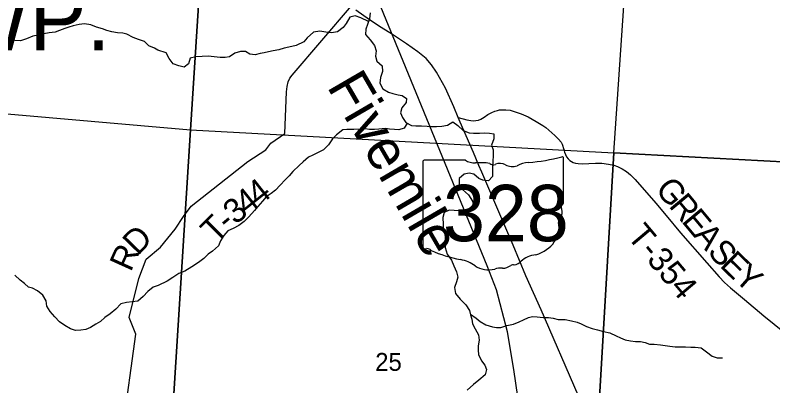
# Model space of a CAD drawing. Extents: x 0 to 34, y 0 to 22.
# Drawn here: x 4.184 to 5.957, y 19.32 to 20.186 of the extents above; entities that cross this region are included whole.
import ezdxf

# ---------------------------------------------------------------- set-up
doc = ezdxf.new("R2010")
doc.units = 0
for name, color, linetype in [('GM_X_Corporation', 7, 'Continuous'), ('GM_X_Minor_River', 7, 'Continuous'), ('GM_X_Minor_River_Text', 7, 'Continuous'), ('GM_X_Rail_Line', 7, 'Continuous'), ('GM_X_Section_Text', 7, 'Continuous'), ('GM_X_State_Location', 7, 'Continuous'), ('GM_X_State_Route', 7, 'Continuous'), ('GM_X_State_Shield', 7, 'Continuous'), ('GM_X_Township_Road', 7, 'Continuous'), ('GM_X_Township_Road_Text', 7, 'Continuous'), ('GM_X_Township_Text', 7, 'Continuous')]:
    doc.layers.add(name, color=color, linetype=linetype)

msp = doc.modelspace()

# ---------------------------------------------------------------- linework, layer by layer
at = {"layer": 'GM_X_Corporation'}
for points in [[(4.6577, 20.9), (3.646, 20.9), (3.5832, 20.0065), (4.594, 19.9182)], [(5.5834, 20.9), (4.6577, 20.9), (4.594, 19.9182), (5.5855, 19.8646), (5.6551, 20.8957), (5.6507, 20.896)], [(5.6551, 20.8957), (6.6504, 20.8365), (6.5798, 19.8114), (5.5855, 19.8646)], [(3.5832, 20.0065), (4.594, 19.9182), (4.5309, 18.9179), (4.5247, 18.9179), (3.5166, 18.9866)], [(4.594, 19.9182), (5.5855, 19.8646), (5.5263, 18.8526), (4.5309, 18.9179)], [(5.5855, 19.8646), (6.5798, 19.8114), (6.5391, 18.7835), (5.5263, 18.8526)]]:
    msp.add_lwpolyline(points, close=True, dxfattribs=at)
at = {"layer": 'GM_X_Minor_River'}
for p, q in [((4.9797, 20.1846), (4.9677, 20.1818)), ((4.9934, 20.1798), (4.9797, 20.1846)), ((4.3339, 20.1647), (4.3195, 20.1616)), ((4.3464, 20.1659), (4.3339, 20.1647)), ((4.3608, 20.1637), (4.3464, 20.1659)), ((4.9587, 20.1669), (4.952, 20.1574)), ((4.9677, 20.1818), (4.9587, 20.1669)), ((5.011, 20.1719), (4.9934, 20.1798)), ((4.2878, 20.1501), (4.2776, 20.1467)), ((4.2999, 20.1551), (4.2878, 20.1501)), ((4.3097, 20.1585), (4.2999, 20.1551)), ((4.3195, 20.1616), (4.3097, 20.1585)), ((4.3744, 20.1585), (4.3608, 20.1637)), ((4.3884, 20.154), (4.3744, 20.1585)), ((4.3987, 20.1502), (4.3884, 20.154)), ((4.4104, 20.1472), (4.3987, 20.1502)), ((4.4233, 20.145), (4.4104, 20.1472)), ((4.8972, 20.1493), (4.8825, 20.1462)), ((4.9108, 20.1468), (4.8972, 20.1493)), ((4.9381, 20.1474), (4.9245, 20.145)), ((4.952, 20.1574), (4.9381, 20.1474)), ((4.2103, 20.1312), (4.1966, 20.1262)), ((4.2254, 20.1373), (4.2103, 20.1312)), ((4.2382, 20.1393), (4.2254, 20.1373)), ((4.2507, 20.1424), (4.2382, 20.1393)), ((4.2636, 20.1451), (4.2507, 20.1424)), ((4.2776, 20.1467), (4.2636, 20.1451)), ((4.4358, 20.144), (4.4233, 20.145)), ((4.4456, 20.1421), (4.4358, 20.144)), ((4.46, 20.1338), (4.4456, 20.1421)), ((4.4729, 20.1297), (4.46, 20.1338)), ((4.4866, 20.1248), (4.4729, 20.1297)), ((4.8671, 20.1331), (4.8596, 20.1236)), ((4.8825, 20.1462), (4.8671, 20.1331)), ((4.9245, 20.145), (4.9108, 20.1468)), ((4.1966, 20.1262), (4.1834, 20.1269)), ((4.4972, 20.115), (4.4866, 20.1248)), ((4.5101, 20.109), (4.4972, 20.115)), ((4.8245, 20.1115), (4.8135, 20.1091)), ((4.8419, 20.1151), (4.8245, 20.1115)), ((4.8596, 20.1236), (4.8419, 20.1151)), ((4.5179, 20.1041), (4.5101, 20.109)), ((4.5371, 20.0983), (4.5179, 20.1041)), ((4.5444, 20.0851), (4.5371, 20.0983)), ((4.6982, 20.0971), (4.6855, 20.089)), ((4.7118, 20.1014), (4.6982, 20.0971)), ((4.7232, 20.1011), (4.7118, 20.1014)), ((4.7335, 20.0952), (4.7232, 20.1011)), ((4.746, 20.0938), (4.7335, 20.0952)), ((4.7573, 20.0965), (4.746, 20.0938)), ((4.7671, 20.0985), (4.7573, 20.0965)), ((4.7769, 20.1009), (4.7671, 20.0985)), ((4.7879, 20.1029), (4.7769, 20.1009)), ((4.8011, 20.1056), (4.7879, 20.1029)), ((4.8135, 20.1091), (4.8011, 20.1056)), ((4.5539, 20.0723), (4.5444, 20.0851)), ((4.5935, 20.0859), (4.5899, 20.0726)), ((4.6068, 20.0891), (4.5935, 20.0859)), ((4.6215, 20.09), (4.6068, 20.0891)), ((4.6355, 20.0905), (4.6215, 20.09)), ((4.6499, 20.0887), (4.6355, 20.0905)), ((4.6639, 20.0873), (4.6499, 20.0887)), ((4.6756, 20.0871), (4.6639, 20.0873)), ((4.6855, 20.089), (4.6756, 20.0871)), ((4.5668, 20.0679), (4.5539, 20.0723)), ((4.5797, 20.065), (4.5668, 20.0679)), ((4.5899, 20.0726), (4.5797, 20.065)), ((4.9507, 19.9179), (4.936, 19.9068)), ((4.9605, 19.9187), (4.9507, 19.9179)), ((4.9768, 19.9189), (4.9605, 19.9187)), ((4.9904, 19.9198), (4.9768, 19.9189)), ((5.0036, 19.9206), (4.9904, 19.9198)), ((5.0135, 19.9192), (5.0036, 19.9206)), ((5.0248, 19.9189), (5.0135, 19.9192)), ((5.035, 19.9194), (5.0248, 19.9189)), ((5.0505, 19.9214), (5.035, 19.9194)), ((5.06, 19.92), (5.0505, 19.9214)), ((5.0721, 19.9186), (5.06, 19.92)), ((5.0823, 19.9183), (5.0721, 19.9186)), ((5.0944, 19.9218), (5.0823, 19.9183)), ((5.1014, 19.9337), (5.0944, 19.9218)), ((4.936, 19.9068), (4.927, 19.8968)), ((4.9173, 19.8835), (4.9057, 19.8716)), ((4.927, 19.8968), (4.9173, 19.8835)), ((4.8932, 19.8655), (4.8804, 19.8593)), ((4.9057, 19.8716), (4.8932, 19.8655)), ((4.8706, 19.8539), (4.8582, 19.8432)), ((4.8804, 19.8593), (4.8706, 19.8539)), ((4.8485, 19.8347), (4.8342, 19.8206)), ((4.8582, 19.8432), (4.8485, 19.8347)), ((4.8252, 19.811), (4.8158, 19.8015)), ((4.8342, 19.8206), (4.8252, 19.811)), ((4.8158, 19.8015), (4.8042, 19.7885)), ((4.7937, 19.7774), (4.7832, 19.769)), ((4.8042, 19.7885), (4.7937, 19.7774)), ((4.7715, 19.7616), (4.7626, 19.7513)), ((4.7832, 19.769), (4.7715, 19.7616)), ((4.7626, 19.7513), (4.7517, 19.7387)), ((4.7442, 19.7292), (4.7311, 19.715)), ((4.7517, 19.7387), (4.7442, 19.7292)), ((4.7202, 19.704), (4.7078, 19.6948)), ((4.7311, 19.715), (4.7202, 19.704)), ((4.6946, 19.6871), (4.6818, 19.682)), ((4.7078, 19.6948), (4.6946, 19.6871)), ((4.6721, 19.6713), (4.6646, 19.6584)), ((4.6818, 19.682), (4.6721, 19.6713)), ((4.6646, 19.6584), (4.6598, 19.6469)), ((4.6459, 19.6343), (4.6361, 19.6278)), ((4.6598, 19.6469), (4.6459, 19.6343)), ((4.6256, 19.6175), (4.6128, 19.6082)), ((4.6361, 19.6278), (4.6256, 19.6175)), ((4.5974, 19.5979), (4.5809, 19.5875)), ((4.6128, 19.6082), (4.5974, 19.5979)), ((4.5669, 19.5824), (4.553, 19.5728)), ((4.5809, 19.5875), (4.5669, 19.5824)), ((4.196, 19.5664), (4.1831, 19.5785)), ((4.2055, 19.5589), (4.196, 19.5664)), ((4.5394, 19.5644), (4.5187, 19.5538)), ((4.553, 19.5728), (4.5394, 19.5644)), ((4.2153, 19.5506), (4.2055, 19.5589)), ((4.2248, 19.5476), (4.2153, 19.5506)), ((4.2366, 19.5416), (4.2248, 19.5476)), ((4.5068, 19.55), (4.4947, 19.5405)), ((4.5187, 19.5538), (4.5068, 19.55)), ((4.2491, 19.5314), (4.2366, 19.5416)), ((4.2567, 19.5186), (4.2491, 19.5314)), ((4.4834, 19.5283), (4.4709, 19.5172)), ((4.4947, 19.5405), (4.4834, 19.5283)), ((4.2583, 19.5061), (4.2567, 19.5186)), ((4.4316, 19.511), (4.4195, 19.4988)), ((4.4444, 19.5141), (4.4316, 19.511)), ((4.4577, 19.516), (4.4444, 19.5141)), ((4.4709, 19.5172), (4.4577, 19.516)), ((4.2662, 19.4936), (4.2583, 19.5061)), ((4.2769, 19.4808), (4.2662, 19.4936)), ((4.4195, 19.4988), (4.4067, 19.4882)), ((4.2875, 19.469), (4.2769, 19.4808)), ((4.3942, 19.4794), (4.3837, 19.4702)), ((4.4067, 19.4882), (4.3942, 19.4794)), ((5.2495, 19.487), (5.2629, 19.4777)), ((5.2629, 19.4777), (5.2724, 19.4699)), ((5.3639, 19.4692), (5.3737, 19.4742)), ((5.3737, 19.4742), (5.3854, 19.4796)), ((5.3854, 19.4796), (5.3952, 19.482)), ((5.3952, 19.482), (5.4058, 19.4806)), ((5.4058, 19.4806), (5.4195, 19.4795)), ((5.4195, 19.4795), (5.4323, 19.4793)), ((5.4323, 19.4793), (5.4429, 19.4775)), ((5.4429, 19.4775), (5.4551, 19.4746)), ((5.4551, 19.4746), (5.4717, 19.4743)), ((5.4717, 19.4743), (5.4865, 19.4714)), ((4.3, 19.4604), (4.2875, 19.469)), ((4.3133, 19.4529), (4.3, 19.4604)), ((4.3606, 19.4557), (4.3497, 19.4515)), ((4.3727, 19.4637), (4.3606, 19.4557)), ((4.3837, 19.4702), (4.3727, 19.4637)), ((5.2724, 19.4699), (5.2857, 19.4624)), ((5.2857, 19.4624), (5.3012, 19.4572)), ((5.3012, 19.4572), (5.3107, 19.4558)), ((5.3107, 19.4558), (5.3205, 19.4563)), ((5.3205, 19.4563), (5.3349, 19.461)), ((5.3349, 19.461), (5.3508, 19.4638)), ((5.3508, 19.4638), (5.3639, 19.4692)), ((5.4865, 19.4714), (5.4994, 19.4681)), ((5.4994, 19.4681), (5.5089, 19.4644)), ((5.5089, 19.4644), (5.5211, 19.4581)), ((5.5211, 19.4581), (5.5347, 19.4537)), ((4.3254, 19.4491), (4.3133, 19.4529)), ((4.3379, 19.4496), (4.3254, 19.4491)), ((4.3497, 19.4515), (4.3379, 19.4496)), ((5.5347, 19.4537), (5.5469, 19.4504)), ((5.5469, 19.4504), (5.5613, 19.4463)), ((5.5613, 19.4463), (5.5761, 19.4431)), ((5.5761, 19.4431), (5.5909, 19.4368)), ((5.5909, 19.4368), (5.6007, 19.4319)), ((5.6007, 19.4319), (5.6114, 19.4275)), ((5.6114, 19.4275), (5.6243, 19.4246)), ((5.6243, 19.4246), (5.636, 19.4231)), ((5.636, 19.4231), (5.6474, 19.4229)), ((5.6474, 19.4229), (5.6587, 19.4207)), ((5.6587, 19.4207), (5.669, 19.417)), ((5.669, 19.417), (5.6799, 19.4171)), ((5.6799, 19.4171), (5.6943, 19.4153)), ((5.6943, 19.4153), (5.7053, 19.4135)), ((5.7053, 19.4135), (5.7163, 19.4121)), ((5.7163, 19.4121), (5.7292, 19.4104)), ((5.7292, 19.4104), (5.753, 19.4106)), ((5.753, 19.4106), (5.7655, 19.4099)), ((5.7655, 19.4099), (5.7754, 19.4096)), ((5.7754, 19.4096), (5.7897, 19.4083)), ((5.7897, 19.4083), (5.8019, 19.3993)), ((5.8019, 19.3993), (5.8153, 19.3888)), ((5.8153, 19.3888), (5.827, 19.3847)), ((5.827, 19.3847), (5.8399, 19.3848))]:
    msp.add_line(p, q, dxfattribs=at)
for points in [[(5.0152, 20.1917), (5.0131, 20.178), (5.0087, 20.1647), (5.0046, 20.1537), (5.004, 20.1408), (5.0147, 20.1284), (5.0254, 20.1156), (5.0289, 20.1031), (5.0275, 20.0906), (5.0306, 20.0785), (5.0432, 20.0677), (5.0441, 20.0548), (5.0393, 20.0407), (5.0375, 20.0274), (5.0444, 20.0139), (5.0577, 20.0064), (5.0676, 20.0031), (5.0805, 19.9998), (5.09, 19.9984), (5.1002, 19.9916), (5.0995, 19.9821), (5.0891, 19.9699), (5.0861, 19.9582), (5.0908, 19.9472), (5.0981, 19.9355), (5.1114, 19.9281), (5.122, 19.9274), (5.1352, 19.9275), (5.1481, 19.9265), (5.1579, 19.9258), (5.17, 19.9256), (5.1829, 19.9264), (5.1961, 19.9292), (5.2082, 19.9369), (5.22, 19.9283), (5.2325, 19.9167), (5.2466, 19.9111), (5.2564, 19.9101), (5.2712, 19.9106), (5.2818, 19.911), (5.2946, 19.9104), (5.3041, 19.909), (5.3046, 19.8969), (5.2987, 19.8824), (5.3029, 19.8711), (5.3031, 19.8574), (5.3017, 19.8449), (5.3014, 19.8313), (5.3015, 19.8184), (5.3012, 19.8089), (5.2918, 19.7986), (5.2786, 19.8004), (5.2691, 19.8044), (5.2573, 19.8146), (5.247, 19.8171), (5.2346, 19.8147), (5.2229, 19.804), (5.2234, 19.7911), (5.2307, 19.7787), (5.2448, 19.766), (5.2548, 19.7516), (5.2564, 19.7388), (5.244, 19.728), (5.2323, 19.7276), (5.2228, 19.729), (5.2115, 19.7293), (5.2001, 19.7303), (5.1884, 19.7249), (5.1847, 19.7135), (5.1856, 19.6972), (5.1861, 19.6866), (5.19, 19.6756), (5.1908, 19.6658), (5.1906, 19.6525), (5.1907, 19.6427), (5.1953, 19.6276), (5.2049, 19.6136), (5.2111, 19.6)], [(5.2111, 19.6), (5.2169, 19.5861), (5.22, 19.574), (5.2171, 19.563), (5.2123, 19.5493), (5.2147, 19.5353), (5.2258, 19.5225), (5.2387, 19.5093), (5.2472, 19.4954), (5.2499, 19.4856), (5.2527, 19.4754), (5.2546, 19.4648), (5.2604, 19.4527), (5.2685, 19.4391), (5.2697, 19.4263), (5.268, 19.4134), (5.2677, 19.4031), (5.2685, 19.3925), (5.2754, 19.3782), (5.2831, 19.368), (5.2874, 19.3578), (5.2841, 19.3449), (5.269, 19.3327), (5.2566, 19.3227), (5.242, 19.3097)]]:
    msp.add_lwpolyline(points, dxfattribs=at)
at = {"layer": 'GM_X_Rail_Line'}
msp.add_lwpolyline([(5.4004, 18.0178), (5.3565, 18.3179), (5.3392, 18.4015), (5.2983, 18.5634), (5.2919, 18.587), (5.2905, 18.6045), (5.2864, 18.6295), (5.2867, 18.6593), (5.2915, 18.6851), (5.3496, 18.8224), (5.3806, 18.8744), (5.3985, 18.9151), (5.4041, 18.9575), (5.4041, 18.9937), (5.4016, 19.0373), (5.3783, 19.1779), (5.37, 19.2302), (5.351, 19.3574), (5.3362, 19.4456), (5.311, 19.5437), (5.2889, 19.5998), (5.0925, 20.0787), (5.0288, 20.2329)], dxfattribs=at)
at = {"layer": 'GM_X_State_Route'}
msp.add_lwpolyline([(5.5021, 19.2979), (5.4152, 19.4973), (5.3972, 19.5369), (5.3796, 19.5766), (5.3493, 19.6481), (5.3322, 19.6881), (5.276, 19.8195), (5.2696, 19.8345), (5.2565, 19.8652), (5.2256, 19.9365), (5.2212, 19.9469), (5.2105, 19.9718), (5.1916, 20.016), (5.1699, 20.0534), (5.1586, 20.0705), (5.1461, 20.0853), (5.1268, 20.1002), (5.0996, 20.1196), (5.067, 20.1414), (5.0406, 20.1578), (5.0133, 20.1753), (4.9815, 20.1978)], dxfattribs=at)
at = {"layer": 'GM_X_State_Shield'}
for p, q in [((5.2377, 19.8471), (5.1412, 19.8471)), ((5.4675, 19.7474), (5.4675, 19.8521)), ((5.1379, 19.8437), (5.1379, 19.6436)), ((5.4675, 19.7474), (5.4675, 19.7474))]:
    msp.add_line(p, q, dxfattribs=at)
for centre, major_axis, start_param, end_param in [((5.1417, 19.8441), (0.00382, 0), 1.712693, 3.28349), ((5.2607, 19.8703), (0.037, 0), 4.042523, 4.731795), ((5.3501, 20.1199), (0.3495, 0), 4.814394, 5.042369), ((5.4638, 19.8525), (0.00367, 0), 6.141152, 7.989035), ((5.2729, 19.7348), (0.133, 0), 1.404758, 1.657858), ((5.3031, 19.8451), (0.0107, 0), 3.836095, 5.185415), ((5.3188, 19.822), (0.0222, 0), 0.950623, 2.079405), ((5.3475, 19.8537), (0.0267, 0), 4.081561, 5.145723), ((5.3947, 19.786), (0.0703, 0), 1.699011, 2.107814), ((5.4666, 19.7397), (0.00568, 0), 1.883978, 3.671073), ((5.4636, 19.747), (0.00393, 0), 5.05454, 6.418171), ((5.4305, 19.7265), (0.0341, 0), 5.934695, 6.695948), ((5.4806, 19.7036), (0.0248, 0), 2.387724, 3.262537), ((5.3697, 19.6903), (0.0874, 0), 5.101752, 6.440018), ((5.1417, 19.6431), (0.00385, 0), 3.00124, 4.508301), ((5.1423, 19.6636), (0.0294, 0), 4.665946, 4.897461), ((5.1483, 19.632), (0.0106, 0), 0.519207, 1.627899), ((5.2821, 19.8118), (0.2524, 0), 4.195997, 4.488961), ((5.2069, 19.5536), (0.079, 0), 0.823519, 1.323587), ((5.4065, 19.5874), (0.0479, 0), 1.647645, 2.488434), ((5.2923, 19.631), (0.0501, 0), 4.026481, 4.996735), ((5.3249, 19.616), (0.0267, 0), 4.691044, 5.507374), ((5.3491, 19.5966), (0.00752, 0), 1.147584, 2.315152), ((5.3459, 19.6242), (0.0282, 0), 4.937069, 5.64225), ((5.3213, 19.5618), (0.0412, 0), 1.495662, 1.94098)]:
    msp.add_ellipse(centre, major_axis=major_axis, ratio=0.8, start_param=start_param, end_param=end_param, dxfattribs=at)
at = {"layer": 'GM_X_Township_Road'}
for points in [[(4.3419, 19.0241), (4.372, 19.0711), (4.3947, 19.1216), (4.4137, 19.1482), (4.43, 19.1766), (4.4357, 19.2192), (4.4663, 19.4401), (4.4508, 19.4795), (4.4731, 19.5702), (4.4909, 19.6154), (4.5239, 19.6439), (4.5586, 19.6856), (4.5781, 19.7159), (4.596, 19.7393), (4.7288, 19.8444), (4.771, 19.8713), (4.7828, 19.887), (4.815, 19.9099), (4.8192, 20.0072), (4.8203, 20.0192), (4.8232, 20.0302), (4.8267, 20.0387), (4.8323, 20.0458), (4.9711, 20.208)], [(5.2212, 19.9469), (5.2292, 19.9447), (5.2324, 19.9439), (5.2411, 19.9415), (5.2502, 19.9399), (5.2564, 19.9395), (5.2624, 19.9399), (5.2684, 19.9411), (5.2741, 19.9432), (5.2817, 19.9479), (5.2901, 19.9537), (5.2994, 19.9585), (5.3068, 19.9617), (5.3128, 19.9636), (5.3176, 19.9647), (5.3231, 19.9652), (5.3324, 19.9652), (5.3423, 19.9638), (5.3543, 19.9606), (5.3684, 19.9554), (5.385, 19.9484), (5.4038, 19.9379), (5.419, 19.9285), (5.4259, 19.9235), (5.4475, 19.9052), (5.4561, 19.8964), (5.4617, 19.8892), (5.464, 19.8845), (5.468, 19.8724), (5.47, 19.8661), (5.4748, 19.8552), (5.4782, 19.8502), (5.4823, 19.8461), (5.4897, 19.8419), (5.4956, 19.8399), (5.5017, 19.8391), (5.511, 19.839), (5.542, 19.8403), (5.5575, 19.8399), (5.5729, 19.8382), (5.585, 19.8358), (5.5937, 19.8328), (5.6048, 19.8273), (5.6152, 19.8207), (5.6246, 19.8127), (5.6349, 19.8021), (5.6839, 19.7469), (5.7077, 19.7182), (5.7411, 19.6772), (5.8026, 19.6073), (5.8315, 19.5747), (5.8444, 19.5613), (5.8583, 19.5489), (5.8913, 19.5213), (5.9364, 19.4835), (5.9846, 19.4445)]]:
    msp.add_lwpolyline(points, dxfattribs=at)

# ---------------------------------------------------------------- texts
at = {"layer": 'GM_X_Minor_River_Text'}
msp.add_text('Fivemile', height=0.0947, rotation=300.1687, dxfattribs=at).set_placement((4.9123, 20.0199))
at = {"layer": 'GM_X_Section_Text'}
msp.add_text('25', height=0.04186, rotation=0, dxfattribs=at).set_placement((5.0267, 19.3546))
at = {"layer": 'GM_X_State_Location'}
for s in ['s', 'r']:
    msp.add_text(s, height=0.000189, dxfattribs=at).set_placement((5.299, 19.7303))
msp.add_text('328', height=0.000189, rotation=0, dxfattribs=at).set_placement((5.2321, 19.7165))
at = {"layer": 'GM_X_State_Shield'}
msp.add_text('328', height=0.13184, dxfattribs=at).set_placement((5.1855, 19.6577))
at = {"layer": 'GM_X_Township_Road_Text'}
for s, height, rotation, p in [('4', 0.0568, 38.2981, (4.7541, 19.7385)), ('G', 0.0568, 309.8569, (5.6801, 19.7781)), ('4', 0.0568, 38.3916, (4.7267, 19.7168)), ('3', 0.0568, 38.8207, (4.6995, 19.6949)), ('R', 0.0568, 309.857, (5.7122, 19.7397)), ('T', 0.0568, 44.9333, (4.6527, 19.651)), ('E', 0.0568, 309.86, (5.7421, 19.7039)), ('-', 0.0568, 39.9655, (4.6818, 19.6801)), ('T-354', 0.05682, 310.0206, (5.6141, 19.6687)), ('D', 0.0568, 45.9196, (4.4709, 19.6223)), ('A', 0.0568, 309.8808, (5.7693, 19.6712)), ('S', 0.0568, 311.4397, (5.8025, 19.6316)), ('R', 0.0568, 65.6436, (4.4545, 19.5841)), ('E', 0.0568, 315.7128, (5.8311, 19.5995)), ('Y', 0.0568, 318.7749, (5.8639, 19.5676))]:
    msp.add_text(s, height=height, rotation=rotation, dxfattribs=at).set_placement(p)
at = {"layer": 'GM_X_Township_Text'}
msp.add_text('TWP.', height=0.15, rotation=0, dxfattribs=at).set_placement((3.9056, 20.1038))

doc.saveas('drawing.dxf')
